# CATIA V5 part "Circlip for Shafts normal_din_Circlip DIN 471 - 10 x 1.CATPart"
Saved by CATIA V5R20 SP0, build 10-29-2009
Part number: Circlip for Shafts normal_din_Circlip DIN 471 - 10 x 1
Revision: ANY
Definition: UNKNOWN
Nomenclature: Circlip for Shafts normal_din_Circlip DIN 471 - 10 x 1
Source: Unknown
Bounding box of the stored display mesh (mm): x -6.081 to 6.081, y -8.096 to 6.448, z -1 to 0
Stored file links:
  C:\Users\Utente\Desktop\IO LAVORO\3D X SITO CF\CUMSA\3D files CX.013058\CX 013058\Circlip for Shafts normal_din_Circlip DIN 471 - 10 x 1.CATPart
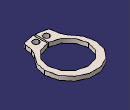
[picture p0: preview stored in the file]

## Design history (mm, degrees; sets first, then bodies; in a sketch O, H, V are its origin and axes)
Body1 "Body" (main body)
  Solid1: solid without history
